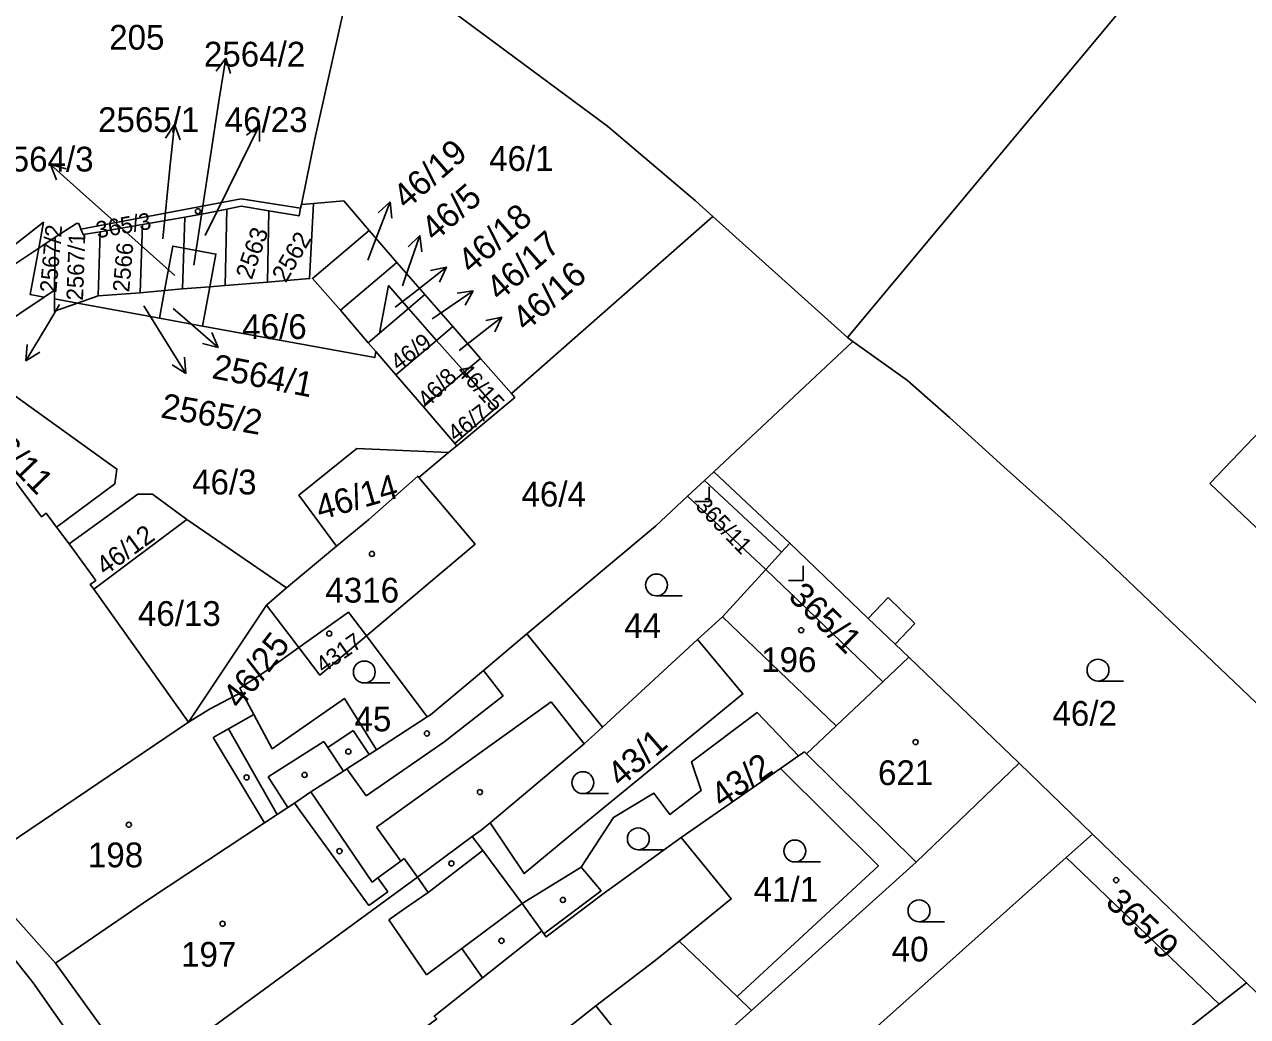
# Model space of a CAD drawing. Extents: x -679220 to -673243, y -1075091 to -1066557.
# Drawn here: x -676508.2 to -676424.2, y -1071318.5 to -1071250.4 of the extents above; entities that cross this region are included whole.
import ezdxf

# ---------------------------------------------------------------- set-up
doc = ezdxf.new("R2010")
doc.units = 0
for name, color, linetype in [('Hranice parcel', 7, 'Continuous'), ('Parcelní čísla', 7, 'Continuous'), ('Pop  PČ popisy', 7, 'Continuous'), ('Vnitřní kresba', 7, 'Continuous'), ('Značky budov', 7, 'Continuous'), ('Značky kultur', 7, 'Continuous')]:
    doc.layers.add(name, color=color, linetype=linetype)

msp = doc.modelspace()

# ---------------------------------------------------------------- linework, layer by layer
at = {"layer": 'Hranice parcel'}
for p, q in [((-676432.68, -1071249.13), (-676451.69, -1071271.9)), ((-676489.21, -1071263.03), (-676489.16, -1071262.78)), ((-676489.16, -1071262.78), (-676488.33, -1071262.71)), ((-676500.07, -1071264.15), (-676497.16, -1071263.64)), ((-676497.16, -1071263.64), (-676497.23, -1071265.77)), ((-676494.28, -1071263.1), (-676494.39, -1071268.33)), ((-676491.4, -1071263.22), (-676491.49, -1071268.1)), ((-676474.75, -1071275.75), (-676460.92, -1071263.61)), ((-676460.92, -1071263.61), (-676451.69, -1071271.9)), ((-676502.97, -1071264.65), (-676500.07, -1071264.15)), ((-676500.21, -1071268.83), (-676500.07, -1071264.15)), ((-676507.18, -1071265.78), (-676506.05, -1071265.03)), ((-676506.09, -1071268.66), (-676506.05, -1071265.03)), ((-676502.97, -1071264.65), (-676503.11, -1071269.05)), ((-676484.51, -1071264.57), (-676482.62, -1071266.76)), ((-676507.18, -1071265.78), (-676512.05, -1071269.01)), ((-676497.23, -1071265.77), (-676497.31, -1071268.57)), ((-676482.62, -1071266.76), (-676486.47, -1071270.04)), ((-676482.62, -1071266.76), (-676480.69, -1071268.95)), ((-676506.09, -1071268.66), (-676506.8, -1071269.13)), ((-676506.09, -1071269.26), (-676506.09, -1071268.66)), ((-676500.21, -1071268.83), (-676498.55, -1071268.68)), ((-676498.55, -1071268.68), (-676498.89, -1071270.58)), ((-676497.31, -1071268.57), (-676498.55, -1071268.68)), ((-676495.45, -1071268.42), (-676497.31, -1071268.57)), ((-676495.45, -1071268.42), (-676495.94, -1071271.12)), ((-676494.39, -1071268.33), (-676495.45, -1071268.42)), ((-676491.49, -1071268.1), (-676494.39, -1071268.33)), ((-676504.53, -1071269.55), (-676506.09, -1071269.26)), ((-676503.11, -1071269.05), (-676504.53, -1071269.55)), ((-676498.89, -1071270.58), (-676504.53, -1071269.55)), ((-676503.11, -1071269.05), (-676500.21, -1071268.83)), ((-676481.81, -1071269.91), (-676480.69, -1071268.95)), ((-676480.69, -1071268.95), (-676478.76, -1071271.15)), ((-676486.47, -1071270.04), (-676484.57, -1071272.26)), ((-676481.81, -1071269.91), (-676483.8, -1071271.61)), ((-676479.88, -1071272.1), (-676481.81, -1071269.91)), ((-676495.94, -1071271.12), (-676498.89, -1071270.58)), ((-676478.76, -1071271.15), (-676479.88, -1071272.1)), ((-676478.76, -1071271.15), (-676476.87, -1071273.34)), ((-676484.57, -1071272.26), (-676483.8, -1071271.61)), ((-676451.69, -1071271.9), (-676451.32, -1071272.17)), ((-676484.04, -1071272.87), (-676484.57, -1071272.26)), ((-676482.67, -1071274.46), (-676484.04, -1071272.87)), ((-676479.88, -1071272.1), (-676482.67, -1071274.46)), ((-676477.96, -1071274.27), (-676479.88, -1071272.1)), ((-676451.32, -1071272.17), (-676460.87, -1071281.13)), ((-676476.87, -1071273.34), (-676477.96, -1071274.27)), ((-676476.87, -1071273.34), (-676474.75, -1071275.75)), ((-676480.77, -1071276.66), (-676482.67, -1071274.46)), ((-676477.96, -1071274.27), (-676480.77, -1071276.66)), ((-676478.64, -1071279.17), (-676480.77, -1071276.66)), ((-676479.07, -1071279.8), (-676478.5, -1071279.33)), ((-676478.5, -1071279.33), (-676478.64, -1071279.17)), ((-676479.07, -1071279.8), (-676481.09, -1071281.5)), ((-676455.65, -1071286.01), (-676460.87, -1071281.13)), ((-676462.66, -1071282.8), (-676457.3, -1071287.82)), ((-676503.4, -1071289.17), (-676497.02, -1071284.39)), ((-676497.02, -1071284.39), (-676490.17, -1071289.08)), ((-676505.1, -1071286.07), (-676505.95, -1071284.91)), ((-676490.17, -1071289.08), (-676486.74, -1071286.21)), ((-676449.27, -1071295.52), (-676457.3, -1071287.82)), ((-676496.91, -1071298.29), (-676503.4, -1071289.17)), ((-676491.56, -1071290.27), (-676490.17, -1071289.08)), ((-676496.91, -1071298.29), (-676491.56, -1071290.27)), ((-676491.56, -1071290.27), (-676489.33, -1071293.18)), ((-676480.53, -1071297.92), (-676484.7, -1071292.37)), ((-676468.5, -1071298.63), (-676473.68, -1071292.23)), ((-676461.97, -1071292.62), (-676468.5, -1071298.63)), ((-676449.27, -1071295.52), (-676447.49, -1071293.84)), ((-676439.91, -1071301.11), (-676447.49, -1071293.84)), ((-676484.01, -1071300.18), (-676480.53, -1071297.92)), ((-676496.91, -1071298.29), (-676511.8, -1071308.36)), ((-676455.05, -1071300.61), (-676456.28, -1071301.47)), ((-676434.88, -1071305.97), (-676439.91, -1071301.11)), ((-676456.28, -1071301.47), (-676463.1, -1071306.2)), ((-676434.88, -1071305.97), (-676436.69, -1071307.58)), ((-676424.32, -1071316.17), (-676434.88, -1071305.97)), ((-676436.69, -1071307.58), (-676426.2, -1071317.64)), ((-676511.8, -1071308.36), (-676506.02, -1071314.83)), ((-676472.52, -1071312.81), (-676472.66, -1071312.61)), ((-676459.26, -1071317.12), (-676463.23, -1071313.31)), ((-676506.02, -1071314.83), (-676500.22, -1071322.85)), ((-676424.32, -1071316.17), (-676426.2, -1071317.64)), ((-676421.58, -1071318.83), (-676424.32, -1071316.17)), ((-676458.28, -1071318.06), (-676459.26, -1071317.12)), ((-676459.7, -1071319.33), (-676458.28, -1071318.06)), ((-676426.2, -1071317.64), (-676430.88, -1071321.3))]:
    msp.add_line(p, q, dxfattribs=at)
for points in [[(-676489.16, -1071262.78), (-676488.24, -1071258.27), (-676485.34, -1071245.3)], [(-676460.92, -1071263.61), (-676462.12, -1071262.53), (-676468.15, -1071257.41), (-676479.77, -1071248.82), (-676485.34, -1071245.3)], [(-676504.28, -1071264.47), (-676493.28, -1071262.4), (-676489.21, -1071263.03)], [(-676488.33, -1071262.71), (-676488.6, -1071267.86), (-676491.49, -1071268.1)], [(-676488.33, -1071262.71), (-676486.25, -1071262.53), (-676484.51, -1071264.57)], [(-676497.16, -1071263.64), (-676495.77, -1071263.4), (-676494.28, -1071263.1)], [(-676494.28, -1071263.1), (-676493.28, -1071262.9), (-676491.4, -1071263.22)], [(-676491.4, -1071263.22), (-676489.32, -1071263.57), (-676489.21, -1071263.03)], [(-676513.24, -1071268.99), (-676506.86, -1071264), (-676507.18, -1071265.78)], [(-676506.05, -1071265.03), (-676504.6, -1071264.09), (-676504.44, -1071264.08), (-676504.28, -1071264.47)], [(-676504.28, -1071264.47), (-676504.12, -1071264.85), (-676502.97, -1071264.65)], [(-676486.47, -1071270.04), (-676488.4, -1071267.85), (-676484.51, -1071264.57)], [(-676507.18, -1071265.78), (-676507.76, -1071268.96), (-676506.8, -1071269.13)], [(-676497.23, -1071265.77), (-676497.99, -1071265.63), (-676498.55, -1071268.68)], [(-676495.45, -1071268.42), (-676495.02, -1071266.18), (-676497.23, -1071265.77)], [(-676483.8, -1071271.61), (-676483.19, -1071268.34), (-676481.81, -1071269.91)], [(-676506.8, -1071269.13), (-676510.24, -1071271.42), (-676512.05, -1071269.01)], [(-676504.53, -1071269.55), (-676506.09, -1071270.1), (-676506.09, -1071269.26)], [(-676484.04, -1071272.87), (-676484.12, -1071273.28), (-676490.02, -1071272.21), (-676495.94, -1071271.12)], [(-676451.32, -1071272.17), (-676447.58, -1071274.85), (-676444.69, -1071277.39), (-676440.96, -1071280.77), (-676437.03, -1071284.3), (-676433.9, -1071287.2), (-676422.71, -1071297.85), (-676421.23, -1071299.37)], [(-676513.57, -1071275.34), (-676513.8, -1071275.07), (-676510.75, -1071274.53), (-676501.82, -1071280.93), (-676501.96, -1071281.94), (-676505.95, -1071284.91)], [(-676478.64, -1071279.17), (-676475.81, -1071276.72), (-676477.96, -1071274.27)], [(-676505.95, -1071284.91), (-676506.66, -1071283.96), (-676506.98, -1071284.2), (-676513.57, -1071275.34)], [(-676474.75, -1071275.75), (-676474.52, -1071276.01), (-676478.5, -1071279.33)], [(-676486.74, -1071286.21), (-676489.33, -1071282.72), (-676485.36, -1071279.51), (-676479.07, -1071279.8)], [(-676460.87, -1071281.13), (-676461.49, -1071281.71), (-676462.66, -1071282.8)], [(-676486.74, -1071286.21), (-676484.52, -1071284.38), (-676481.17, -1071281.41), (-676481.09, -1071281.5)], [(-676481.09, -1071281.5), (-676477.24, -1071286.09), (-676484.7, -1071292.37)], [(-676505.1, -1071286.07), (-676500.38, -1071282.65), (-676499.38, -1071282.65), (-676497.02, -1071284.39)], [(-676462.66, -1071282.8), (-676464.86, -1071284.84), (-676473.68, -1071292.23)], [(-676503.4, -1071289.17), (-676503.64, -1071288.84), (-676503.27, -1071288.57), (-676505.1, -1071286.07)], [(-676455.65, -1071286.01), (-676456.22, -1071286.64), (-676457.3, -1071287.82)], [(-676447.49, -1071293.84), (-676448.43, -1071292.94), (-676450.27, -1071291.17), (-676455.65, -1071286.01)], [(-676457.3, -1071287.82), (-676460.27, -1071291.06), (-676461.97, -1071292.62)], [(-676400.64, -1071480.43), (-676404.65, -1071473.51), (-676415.78, -1071453.37), (-676425.35, -1071436.91), (-676444.25, -1071404.92), (-676453.53, -1071391.57), (-676458.63, -1071385.05), (-676473.24, -1071365.27), (-676485.03, -1071348.15), (-676497.15, -1071331.02), (-676507.56, -1071316.17), (-676512.86, -1071309.51), (-676528.01, -1071291.25), (-676530.94, -1071288.81)], [(-676489.33, -1071293.18), (-676485.93, -1071290.74), (-676484.7, -1071292.37)], [(-676484.7, -1071292.37), (-676487.89, -1071295.06), (-676489.33, -1071293.18)], [(-676473.68, -1071292.23), (-676476.67, -1071294.74), (-676480.3, -1071297.78), (-676480.53, -1071297.92)], [(-676461.97, -1071292.62), (-676458.86, -1071296.35), (-676469.73, -1071305.25), (-676473.88, -1071308.68), (-676476.2, -1071305.19)], [(-676489.33, -1071293.18), (-676491.59, -1071294.8), (-676493.39, -1071295.96), (-676493.24, -1071296.23)], [(-676455.05, -1071300.61), (-676454.64, -1071300.33), (-676454.51, -1071300.46), (-676452.47, -1071298.54), (-676449.27, -1071295.52)], [(-676493.24, -1071296.23), (-676495.46, -1071297.39), (-676496.91, -1071298.29)], [(-676484.01, -1071300.18), (-676486.21, -1071296.66), (-676491.16, -1071300.12), (-676492.42, -1071297.77), (-676493.24, -1071296.23)], [(-676472.52, -1071312.81), (-676468.6, -1071309.86), (-676469.97, -1071308.24), (-676467.74, -1071304.83), (-676464.97, -1071303.17), (-676463.88, -1071304.62), (-676461.73, -1071302.99), (-676462.39, -1071301.01), (-676457.88, -1071297.64), (-676455.05, -1071300.61)], [(-676476.2, -1071305.19), (-676469.75, -1071299.78), (-676468.5, -1071298.63)], [(-676506.02, -1071314.83), (-676499.57, -1071310.42), (-676491.68, -1071305.2), (-676490.81, -1071304.62), (-676490.1, -1071304.15), (-676489.64, -1071303.84), (-676488.51, -1071303.07), (-676486.28, -1071301.65), (-676486.04, -1071301.49), (-676484.51, -1071300.51), (-676484.01, -1071300.18)], [(-676458.28, -1071318.06), (-676446.97, -1071307.9), (-676439.91, -1071301.11)], [(-676456.28, -1071301.47), (-676449.57, -1071308.14), (-676459.26, -1071317.12)], [(-676476.2, -1071305.19), (-676476.83, -1071305.69), (-676477.43, -1071306.13)], [(-676477.43, -1071306.13), (-676481.2, -1071308.93), (-676500.22, -1071322.85)], [(-676472.66, -1071312.61), (-676474.01, -1071310.72), (-676476.7, -1071307.09), (-676477.43, -1071306.13)], [(-676463.1, -1071306.2), (-676468.45, -1071310.06), (-676472.37, -1071313.02), (-676472.52, -1071312.81)], [(-676463.23, -1071313.31), (-676459.66, -1071310.42), (-676463.1, -1071306.2)], [(-676436.69, -1071307.58), (-676450.91, -1071320.28), (-676455.75, -1071324.77)], [(-676472.66, -1071312.61), (-676476.74, -1071315.84), (-676480.05, -1071318.46), (-676479.87, -1071318.65), (-676483.21, -1071321.14), (-676484.16, -1071321.81), (-676495.45, -1071329.66)], [(-676463.23, -1071313.31), (-676464.89, -1071314.65), (-676468.96, -1071317.75), (-676475.31, -1071322.79), (-676479.35, -1071326.09), (-676479.48, -1071325.94), (-676480.56, -1071326.77), (-676491.54, -1071335.21)]]:
    msp.add_lwpolyline(points, dxfattribs=at)
at = {"layer": 'Pop  PČ popisy'}
for p, q in [((-676494.351, -1071252.736), (-676495.002, -1071253.647)), ((-676494.82, -1071255.7), (-676494.351, -1071252.736)), ((-676494.351, -1071252.736), (-676494.013, -1071253.803)), ((-676496.54, -1071266.94), (-676494.82, -1071255.7)), ((-676497.876, -1071257.295), (-676498.479, -1071258.239)), ((-676498.19, -1071260.28), (-676497.876, -1071257.295)), ((-676497.876, -1071257.295), (-676497.483, -1071258.344)), ((-676493.35, -1071260.04), (-676492.034, -1071257.343)), ((-676492.034, -1071257.343), (-676492.924, -1071258.023)), ((-676492.034, -1071257.343), (-676492.023, -1071258.462)), ((-676504.14, -1071262.05), (-676506.37, -1071260.042)), ((-676506.37, -1071260.042), (-676505.291, -1071260.34)), ((-676506.37, -1071260.042), (-676505.961, -1071261.084)), ((-676498.66, -1071265.13), (-676498.19, -1071260.28)), ((-676495.75, -1071264.9), (-676493.35, -1071260.04)), ((-676497.84, -1071267.65), (-676504.14, -1071262.05)), ((-676484.14, -1071265.4), (-676483.065, -1071262.598)), ((-676483.065, -1071262.598), (-676483.891, -1071263.354)), ((-676483.065, -1071262.598), (-676482.956, -1071263.713)), ((-676482.01, -1071267.75), (-676481.033, -1071264.913)), ((-676481.033, -1071264.913), (-676481.832, -1071265.696)), ((-676481.033, -1071264.913), (-676480.886, -1071266.022)), ((-676484.6, -1071266.6), (-676484.14, -1071265.4)), ((-676482.22, -1071268.36), (-676482.01, -1071267.75)), ((-676481.56, -1071268.94), (-676479.195, -1071267.092)), ((-676479.195, -1071267.092), (-676480.293, -1071267.314)), ((-676479.195, -1071267.092), (-676479.676, -1071268.104)), ((-676479.85, -1071270.39), (-676477.362, -1071268.712)), ((-676477.362, -1071268.712), (-676478.472, -1071268.857)), ((-676477.362, -1071268.712), (-676477.912, -1071269.687)), ((-676482.72, -1071269.83), (-676481.56, -1071268.94)), ((-676505.75, -1071269.64), (-676506.51, -1071270.93)), ((-676499.98, -1071269.73), (-676498.67, -1071271.83)), ((-676497.96, -1071269.91), (-676497.13, -1071270.62)), ((-676480.19, -1071270.62), (-676479.85, -1071270.39)), ((-676506.51, -1071270.93), (-676508.056, -1071273.502)), ((-676497.13, -1071270.62), (-676494.865, -1071272.589)), ((-676477.78, -1071272.36), (-676475.415, -1071270.512)), ((-676475.415, -1071270.512), (-676476.513, -1071270.734)), ((-676475.415, -1071270.512), (-676475.896, -1071271.524)), ((-676498.67, -1071271.83), (-676497.08, -1071274.375)), ((-676494.865, -1071272.589), (-676495.292, -1071271.554)), ((-676508.056, -1071273.502), (-676507.969, -1071272.386)), ((-676508.056, -1071273.502), (-676507.111, -1071272.902)), ((-676494.865, -1071272.589), (-676495.949, -1071272.31)), ((-676478.34, -1071272.8), (-676477.78, -1071272.36)), ((-676497.08, -1071274.375), (-676497.186, -1071273.26)), ((-676497.08, -1071274.375), (-676498.035, -1071273.791))]:
    msp.add_line(p, q, dxfattribs=at)
at = {"layer": 'Vnitřní kresba'}
for p, q in [((-676426.83, -1071281.92), (-676418.54, -1071273.24)), ((-676461.49, -1071281.71), (-676456.22, -1071286.64)), ((-676426.83, -1071281.92), (-676418.28, -1071290.04)), ((-676450.27, -1071291.17), (-676448.9, -1071289.75)), ((-676448.9, -1071289.75), (-676447.06, -1071291.52)), ((-676452.47, -1071298.54), (-676460.27, -1071291.06)), ((-676447.06, -1071291.52), (-676448.43, -1071292.94)), ((-676476.67, -1071294.74), (-676475.31, -1071296.48)), ((-676484.01, -1071305.5), (-676472.02, -1071296.9)), ((-676475.31, -1071296.48), (-676479.39, -1071299.67)), ((-676469.75, -1071299.78), (-676472.02, -1071296.9)), ((-676494.16, -1071298.75), (-676492.42, -1071297.77)), ((-676495.21, -1071299.34), (-676494.16, -1071298.75)), ((-676494.16, -1071298.75), (-676490.81, -1071304.62)), ((-676487.35, -1071300.03), (-676485.6, -1071298.87)), ((-676485.6, -1071298.87), (-676484.51, -1071300.51)), ((-676495.21, -1071299.34), (-676491.68, -1071305.2)), ((-676487.63, -1071299.61), (-676491.44, -1071302.05)), ((-676487.35, -1071300.03), (-676487.63, -1071299.61)), ((-676479.39, -1071299.67), (-676484.71, -1071303.35)), ((-676486.28, -1071301.65), (-676487.35, -1071300.03)), ((-676446.97, -1071307.9), (-676454.51, -1071300.46)), ((-676491.44, -1071302.05), (-676490.1, -1071304.15)), ((-676484.71, -1071303.35), (-676486.04, -1071301.49)), ((-676484.31, -1071309.27), (-676488.51, -1071303.07)), ((-676484.54, -1071310.87), (-676489.64, -1071303.84)), ((-676482.34, -1071307.82), (-676484.01, -1071305.5)), ((-676480.47, -1071309.98), (-676476.7, -1071307.09)), ((-676482.34, -1071307.82), (-676483.91, -1071308.98)), ((-676482.1, -1071307.64), (-676482.34, -1071307.82)), ((-676481.2, -1071308.93), (-676482.1, -1071307.64)), ((-676483.91, -1071308.98), (-676484.31, -1071309.27)), ((-676483.91, -1071308.98), (-676483.23, -1071309.92)), ((-676480.47, -1071309.98), (-676481.2, -1071308.93)), ((-676474.01, -1071310.72), (-676469.97, -1071308.24)), ((-676483.23, -1071309.92), (-676484.54, -1071310.87)), ((-676482.06, -1071311.08), (-676480.47, -1071309.98)), ((-676483.15, -1071311.86), (-676482.06, -1071311.08)), ((-676478.14, -1071313.81), (-676474.01, -1071310.72)), ((-676480.57, -1071315.63), (-676483.15, -1071311.86)), ((-676480.57, -1071315.63), (-676478.14, -1071313.81)), ((-676476.74, -1071315.84), (-676478.14, -1071313.81)), ((-676468.96, -1071317.75), (-676466.5, -1071320.79))]:
    msp.add_line(p, q, dxfattribs=at)
at = {"layer": 'Značky budov'}
for centre in [(-676496.257, -1071263.249), (-676484.317, -1071286.749), (-676487.247, -1071292.219), (-676454.867, -1071291.989), (-676480.547, -1071299.069), (-676447.017, -1071299.659), (-676485.937, -1071300.309), (-676492.917, -1071302.079), (-676488.937, -1071301.909), (-676476.907, -1071303.089), (-676500.997, -1071305.329), (-676486.547, -1071307.139), (-676478.867, -1071307.979), (-676433.257, -1071309.129), (-676471.217, -1071310.489), (-676494.567, -1071312.119), (-676475.427, -1071313.289)]:
    msp.add_circle(centre, 0.175, dxfattribs=at)
at = {"layer": 'Značky kultur'}
for p, q in [((-676461.17, -1071283.16), (-676461.17, -1071282.16)), ((-676462.171, -1071283.16), (-676461.17, -1071283.16)), ((-676454.73, -1071288.57), (-676454.73, -1071287.57)), ((-676455.731, -1071288.57), (-676454.73, -1071288.57)), ((-676464.793, -1071289.63), (-676463.043, -1071289.63)), ((-676434.503, -1071295.47), (-676432.753, -1071295.47)), ((-676484.843, -1071295.6), (-676483.093, -1071295.6)), ((-676469.843, -1071303.19), (-676468.093, -1071303.19)), ((-676466.043, -1071307.04), (-676464.293, -1071307.04)), ((-676455.303, -1071307.88), (-676453.553, -1071307.88)), ((-676446.783, -1071311.98), (-676445.033, -1071311.98))]:
    msp.add_line(p, q, dxfattribs=at)
for centre in [(-676464.793, -1071288.88), (-676484.843, -1071294.85), (-676434.503, -1071294.72), (-676469.843, -1071302.44), (-676466.043, -1071306.29), (-676455.303, -1071307.13), (-676446.783, -1071311.23)]:
    msp.add_circle(centre, 0.75, dxfattribs=at)

# ---------------------------------------------------------------- texts
at = {"layer": 'Parcelní čísla'}
for s, p in [('205', (-676502.345, -1071252.16)), ('2564/2', (-676495.847, -1071253.32)), ('2565/1', (-676503.11, -1071257.81)), ('46/23', (-676494.42, -1071257.82)), ('2564/3', (-676510.367, -1071260.519)), ('46/1', (-676476.279, -1071260.479)), ('46/6', (-676493.219, -1071272.009)), ('46/3', (-676496.659, -1071282.67)), ('46/4', (-676474.059, -1071283.499)), ('4316', (-676487.514, -1071290.09)), ('46/13', (-676500.378, -1071291.69)), ('44', (-676467.006, -1071292.519)), ('196', (-676457.615, -1071294.86)), ('45', (-676485.516, -1071298.92)), ('46/2', (-676437.629, -1071298.54)), ('621', (-676449.595, -1071302.61)), ('198', (-676503.805, -1071308.249)), ('41/1', (-676458.129, -1071310.61)), ('40', (-676448.656, -1071314.71)), ('197', (-676497.415, -1071315.07))]:
    msp.add_text(s, height=1.7, dxfattribs=at).set_placement(p)
for s, height, rotation, p in [('46/19', 1.7, 41, (-676481.952, -1071263.181)), ('46/5', 1.7, 41, (-676480.012, -1071265.391)), ('46/18', 1.7, 41, (-676477.502, -1071267.601)), ('365/3', 1.14, 10, (-676503.149, -1071265.105)), ('2567/2', 1.14, 85, (-676505.972, -1071268.866)), ('2563', 1.2, 71, (-676492.566, -1071267.99)), ('2567/1', 1.14, 88, (-676504.142, -1071269.385)), ('2562', 1.2, 60, (-676490.22, -1071268.208)), ('46/17', 1.7, 41, (-676475.552, -1071269.471)), ('2566', 1.14, 85, (-676500.976, -1071268.826)), ('46/16', 1.7, 41, (-676473.762, -1071271.551)), ('46/9', 1.14, 37, (-676482.495, -1071274.234)), ('2564/1', 1.7, 349, (-676495.363, -1071274.686)), ('46/8', 1.14, 45, (-676480.503, -1071276.789)), ('46/15', 1.14, 313, (-676478.555, -1071274.291)), ('2565/2', 1.7, 350, (-676498.874, -1071277.385)), ('46/7', 1.14, 37, (-676478.575, -1071279.104)), ('46/11', 1.7, 314, (-676511.202, -1071278.707)), ('46/14', 1.7, 16, (-676487.876, -1071284.446)), ('365/11', 1.14, 314, (-676462.188, -1071283.521)), ('46/12', 1.3, 36, (-676502.628, -1071288.278)), ('365/1', 1.7, 316, (-676455.833, -1071289.76)), ('46/25', 1.7, 52, (-676493.37, -1071297.472)), ('4317', 1.139, 35, (-676487.655, -1071294.979)), ('43/1', 1.7, 41, (-676467.241, -1071302.809)), ('43/2', 1.7, 35, (-676460.302, -1071304.235)), ('365/9', 1.7, 316, (-676434.073, -1071310.75))]:
    msp.add_text(s, height=height, rotation=rotation, dxfattribs=at).set_placement(p)

doc.saveas('drawing.dxf')
